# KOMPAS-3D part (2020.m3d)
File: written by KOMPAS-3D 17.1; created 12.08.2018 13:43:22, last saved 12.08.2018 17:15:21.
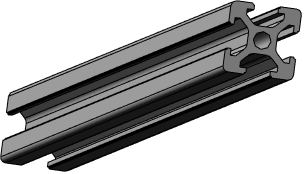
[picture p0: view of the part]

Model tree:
1. Эскиз:1
2. Элемент выдавливания:1
     Расстояние 1 = 450
3. Скругление:1
     Радиус = 1.5
4. Скругление:2
     Радиус = 2
5. Скругление:3  (labels: АД31 ГОСТ 4784-97; SYSTEM_PROPERTY_ADDITIONAL_FOR:9.000000)
     Радиус = 0.2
